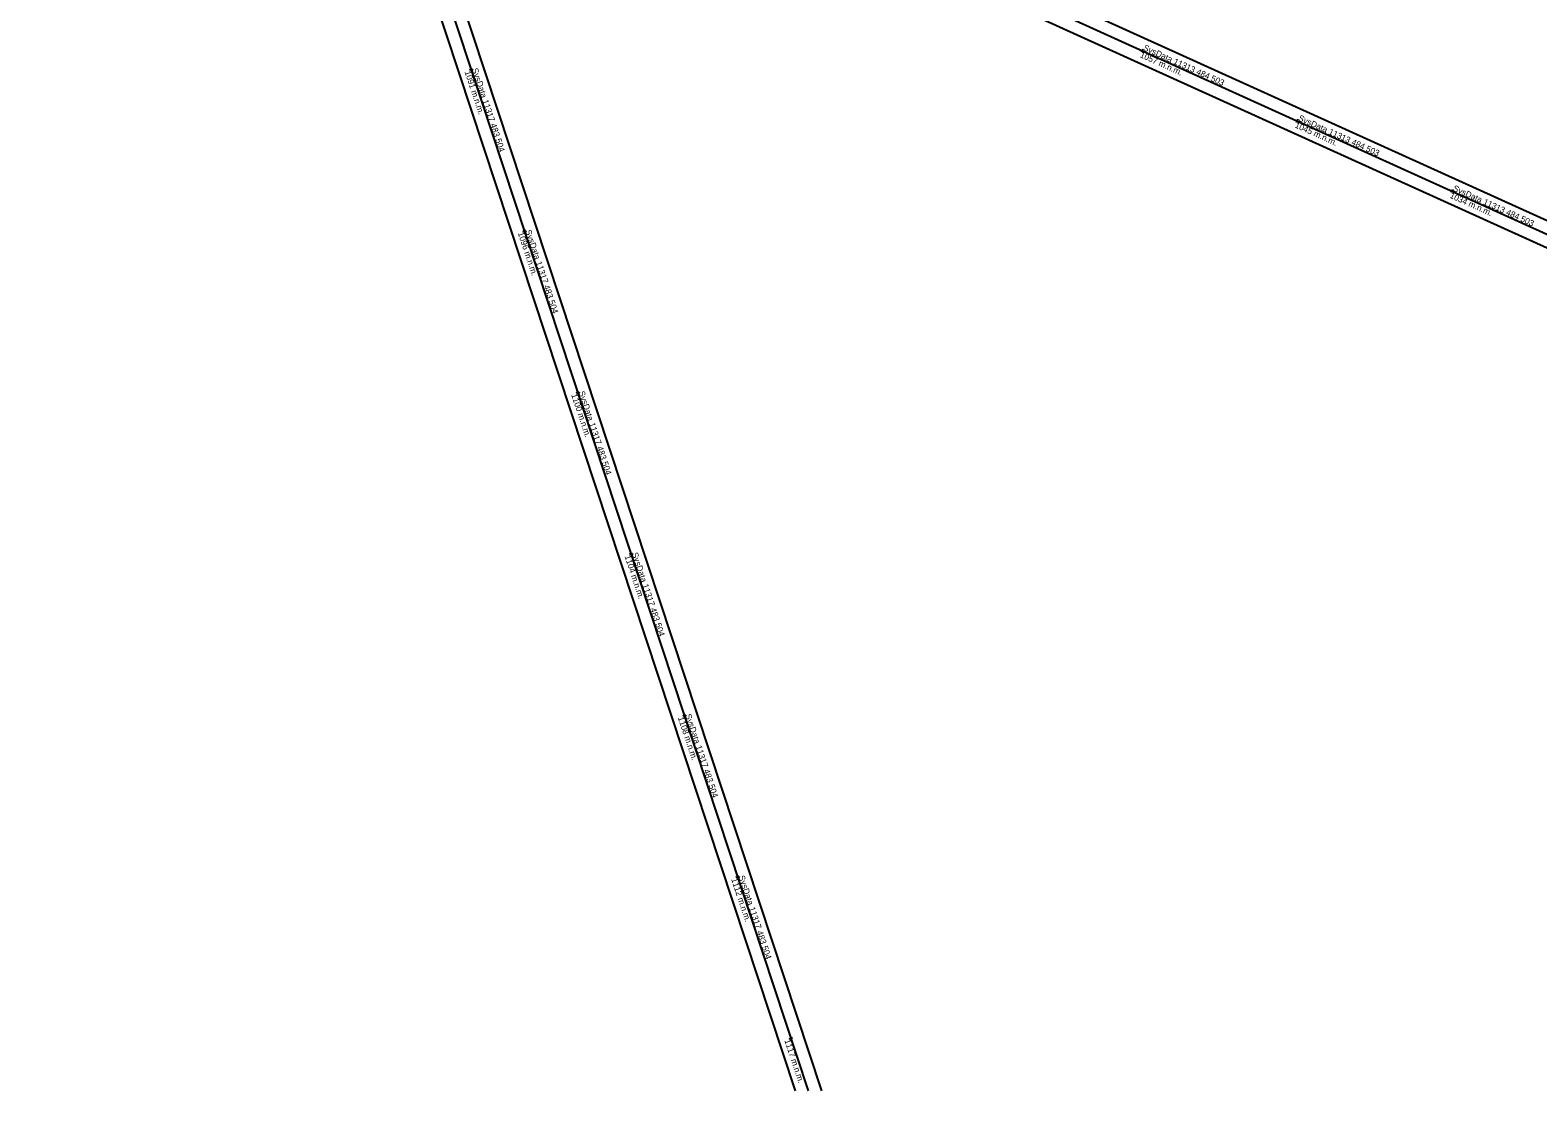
# Model space of a CAD drawing. Extents: x -651139 to -648154, y -984180 to -982978.
# Drawn here: x -650522 to -649635, y -984180 to -983557 of the extents above; entities that cross this region are included whole.
import ezdxf

# ---------------------------------------------------------------- set-up
doc = ezdxf.new("R2010")
doc.units = 0
doc.layers.add('Vrstva 1', color=7, linetype='Continuous')

msp = doc.modelspace()

# ---------------------------------------------------------------- linework, layer by layer
at = {"layer": 'Vrstva 1'}
for p, q in [((-650469.03, -982978.2), (-650072.12, -984180.43)), ((-650461.27, -982978.2), (-650064.36, -984180.43)), ((-650453.51, -982978.2), (-650056.6, -984180.43)), ((-650957.84, -983066.12), (-648502.2, -984180.43)), ((-650960.86, -983072.77), (-648519.87, -984180.43)), ((-650963.88, -983079.42), (-648537.54, -984180.43)), ((-649867.69, -983567.73), (-649868.52, -983569.55)), ((-650263.64, -983580.01), (-650261.74, -983579.38)), ((-649776.63, -983609.05), (-649777.45, -983610.87)), ((-649685.56, -983650.37), (-649686.39, -983652.19)), ((-650232.29, -983674.97), (-650230.39, -983674.34)), ((-650200.94, -983769.92), (-650199.04, -983769.3)), ((-650169.59, -983864.88), (-650167.69, -983864.26)), ((-650138.24, -983959.84), (-650136.34, -983959.22)), ((-650106.89, -984054.8), (-650104.99, -984054.17)), ((-650075.54, -984149.76), (-650073.64, -984149.13))]:
    msp.add_line(p, q, dxfattribs=at)

# ---------------------------------------------------------------- texts
for s, rotation, p in [('1057 m.n.m.', 335.59257, (-649869.72, -983572.4)), ('SysData 11313 484 503', 335.59257, (-649867.81, -983568.22)), ('1091 m.n.m.', 288.27029, (-650266.51, -983581.19)), ('SysData 11317 483 504', 288.27029, (-650262.2, -983579.59)), ('SysData 11313 484 503', 335.59257, (-649776.61, -983609.6)), ('1045 m.n.m.', 335.59257, (-649778.63, -983613.74)), ('SysData 11313 484 503', 335.59257, (-649685.71, -983650.85)), ('1034 m.n.m.', 335.59257, (-649687.55, -983655.07)), ('1096 m.n.m.', 288.27029, (-650235.22, -983675.99)), ('SysData 11317 483 504', 288.27029, (-650230.83, -983674.61)), ('1100 m.n.m.', 288.27029, (-650203.83, -983771.06)), ('SysData 11317 483 504', 288.27029, (-650199.5, -983769.5)), ('SysData 11317 483 504', 288.27029, (-650168.16, -983864.44)), ('1104 m.n.m.', 288.27029, (-650172.47, -983866.04)), ('1108 m.n.m.', 288.27029, (-650141.12, -983961)), ('SysData 11317 483 504', 288.27029, (-650136.81, -983959.38)), ('1112 m.n.m.', 288.27029, (-650109.77, -984055.98)), ('SysData 11317 483 504', 288.27029, (-650105.46, -984054.35)), ('1117 m.n.m.', 288.27029, (-650078.46, -984150.8))]:
    msp.add_text(s, height=3.6, rotation=rotation, dxfattribs=at).set_placement(p)

doc.saveas('drawing.dxf')
